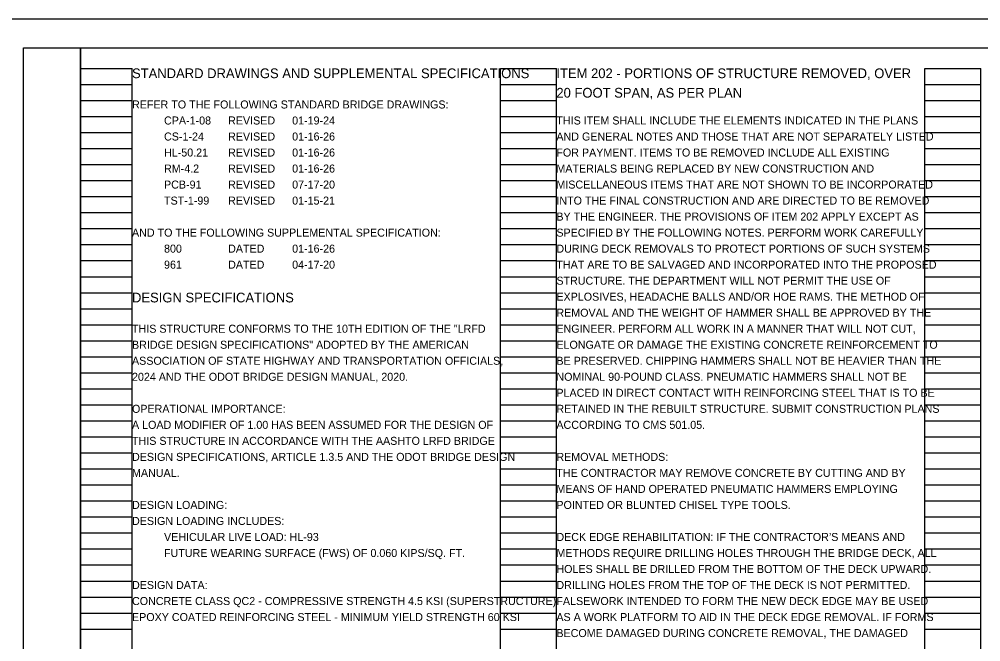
# Model space of a CAD drawing. Extents: x -16.5 to 61.9, y -20 to 22.7.
# Drawn here: x 0.43 to 17.24, y 11.12 to 22 of the extents above; entities that cross this region are included whole.
import ezdxf

# ---------------------------------------------------------------- set-up
doc = ezdxf.new("R2010")
doc.units = 0
for name, color, linetype in [('SH_Border', 7, 'Continuous'), ('SH_Cut_Line', 7, 'Continuous'), ('SH_Data', 7, 'Continuous'), ('SH_Text', 7, 'Continuous')]:
    doc.layers.add(name, color=color, linetype=linetype)

msp = doc.modelspace()

# ---------------------------------------------------------------- linework, layer by layer
at = {"layer": 'SH_Border'}
for points in [[(0.5, 21.5), (1.5, 21.5), (1.5, 0.5), (0.5, 0.5)], [(1.5, 21.5), (33.5, 21.5), (33.5, 0.5), (1.5, 0.5)]]:
    msp.add_lwpolyline(points, close=True, dxfattribs=at)
at = {"layer": 'SH_Cut_Line'}
msp.add_lwpolyline([(0, 0), (34, 0), (34, 22), (0, 22)], close=True, dxfattribs=at)
at = {"layer": 'SH_Data'}
for p, q in [((1.5, 0.98), (1.5, 21.14)), ((1.5, 21.14), (2.4, 21.14)), ((2.4, 0.98), (2.4, 21.14)), ((8.84, 0.98), (8.84, 21.14)), ((8.84, 21.14), (9.82, 21.14)), ((9.82, 0.98), (9.82, 21.14)), ((16.26, 0.98), (16.26, 21.14)), ((16.26, 21.14), (17.24, 21.14)), ((17.24, 0.98), (17.24, 21.14)), ((1.5, 20.86), (2.4, 20.86)), ((8.84, 20.86), (9.82, 20.86)), ((16.26, 20.86), (17.24, 20.86)), ((1.5, 20.58), (2.4, 20.58)), ((8.84, 20.58), (9.82, 20.58)), ((16.26, 20.58), (17.24, 20.58)), ((1.5, 20.3), (2.4, 20.3)), ((8.84, 20.3), (9.82, 20.3)), ((16.26, 20.3), (17.24, 20.3)), ((1.5, 20.02), (2.4, 20.02)), ((8.84, 20.02), (9.82, 20.02)), ((16.26, 20.02), (17.24, 20.02)), ((1.5, 19.74), (2.4, 19.74)), ((8.84, 19.74), (9.82, 19.74)), ((16.26, 19.74), (17.24, 19.74)), ((1.5, 19.46), (2.4, 19.46)), ((8.84, 19.46), (9.82, 19.46)), ((16.26, 19.46), (17.24, 19.46)), ((1.5, 19.18), (2.4, 19.18)), ((8.84, 19.18), (9.82, 19.18)), ((16.26, 19.18), (17.24, 19.18)), ((1.5, 18.9), (2.4, 18.9)), ((8.84, 18.9), (9.82, 18.9)), ((16.26, 18.9), (17.24, 18.9)), ((1.5, 18.62), (2.4, 18.62)), ((8.84, 18.62), (9.82, 18.62)), ((16.26, 18.62), (17.24, 18.62)), ((1.5, 18.34), (2.4, 18.34)), ((8.84, 18.34), (9.82, 18.34)), ((16.26, 18.34), (17.24, 18.34)), ((1.5, 18.06), (2.4, 18.06)), ((8.84, 18.06), (9.82, 18.06)), ((16.26, 18.06), (17.24, 18.06)), ((1.5, 17.78), (2.4, 17.78)), ((8.84, 17.78), (9.82, 17.78)), ((16.26, 17.78), (17.24, 17.78)), ((1.5, 17.5), (2.4, 17.5)), ((8.84, 17.5), (9.82, 17.5)), ((16.26, 17.5), (17.24, 17.5)), ((1.5, 17.22), (2.4, 17.22)), ((8.84, 17.22), (9.82, 17.22)), ((16.26, 17.22), (17.24, 17.22)), ((1.5, 16.94), (2.4, 16.94)), ((8.84, 16.94), (9.82, 16.94)), ((16.26, 16.94), (17.24, 16.94)), ((1.5, 16.66), (2.4, 16.66)), ((8.84, 16.66), (9.82, 16.66)), ((16.26, 16.66), (17.24, 16.66)), ((1.5, 16.38), (2.4, 16.38)), ((8.84, 16.38), (9.82, 16.38)), ((16.26, 16.38), (17.24, 16.38)), ((1.5, 16.1), (2.4, 16.1)), ((8.84, 16.1), (9.82, 16.1)), ((16.26, 16.1), (17.24, 16.1)), ((1.5, 15.82), (2.4, 15.82)), ((8.84, 15.82), (9.82, 15.82)), ((16.26, 15.82), (17.24, 15.82)), ((1.5, 15.54), (2.4, 15.54)), ((8.84, 15.54), (9.82, 15.54)), ((16.26, 15.54), (17.24, 15.54)), ((1.5, 15.26), (2.4, 15.26)), ((8.84, 15.26), (9.82, 15.26)), ((16.26, 15.26), (17.24, 15.26)), ((1.5, 14.98), (2.4, 14.98)), ((8.84, 14.98), (9.82, 14.98)), ((16.26, 14.98), (17.24, 14.98)), ((1.5, 14.7), (2.4, 14.7)), ((8.84, 14.7), (9.82, 14.7)), ((16.26, 14.7), (17.24, 14.7)), ((1.5, 14.42), (2.4, 14.42)), ((8.84, 14.42), (9.82, 14.42)), ((16.26, 14.42), (17.24, 14.42)), ((1.5, 14.14), (2.4, 14.14)), ((8.84, 14.14), (9.82, 14.14)), ((16.26, 14.14), (17.24, 14.14)), ((1.5, 13.86), (2.4, 13.86)), ((8.84, 13.86), (9.82, 13.86)), ((16.26, 13.86), (17.24, 13.86)), ((1.5, 13.58), (2.4, 13.58)), ((8.84, 13.58), (9.82, 13.58)), ((16.26, 13.58), (17.24, 13.58)), ((1.5, 13.3), (2.4, 13.3)), ((8.84, 13.3), (9.82, 13.3)), ((16.26, 13.3), (17.24, 13.3)), ((1.5, 13.02), (2.4, 13.02)), ((8.84, 13.02), (9.82, 13.02)), ((16.26, 13.02), (17.24, 13.02)), ((1.5, 12.74), (2.4, 12.74)), ((8.84, 12.74), (9.82, 12.74)), ((16.26, 12.74), (17.24, 12.74)), ((1.5, 12.46), (2.4, 12.46)), ((8.84, 12.46), (9.82, 12.46)), ((16.26, 12.46), (17.24, 12.46)), ((1.5, 12.18), (2.4, 12.18)), ((8.84, 12.18), (9.82, 12.18)), ((16.26, 12.18), (17.24, 12.18)), ((1.5, 11.9), (2.4, 11.9)), ((8.84, 11.9), (9.82, 11.9)), ((16.26, 11.9), (17.24, 11.9)), ((1.5, 11.62), (2.4, 11.62)), ((8.84, 11.62), (9.82, 11.62)), ((16.26, 11.62), (17.24, 11.62)), ((1.5, 11.34), (2.4, 11.34)), ((8.84, 11.34), (9.82, 11.34)), ((16.26, 11.34), (17.24, 11.34))]:
    msp.add_line(p, q, dxfattribs=at)

# ---------------------------------------------------------------- texts
at = {"layer": 'SH_Text'}
for s, height, p in [('STANDARD DRAWINGS AND SUPPLEMENTAL SPECIFICATIONS', 0.17, (2.4, 20.97)), ('ITEM 202 - PORTIONS OF STRUCTURE REMOVED, OVER ', 0.17, (9.82, 20.97)), ('20 FOOT SPAN, AS PER PLAN', 0.17, (9.82, 20.63)), ('REFER TO THE FOLLOWING STANDARD BRIDGE DRAWINGS:', 0.14, (2.4, 20.44)), ('CPA-1-08', 0.14, (2.96, 20.16)), ('REVISED', 0.14, (4.08, 20.16)), ('01-19-24', 0.14, (5.2, 20.16)), ('THIS ITEM SHALL INCLUDE THE ELEMENTS INDICATED IN THE PLANS ', 0.14, (9.82, 20.16)), ('CS-1-24', 0.14, (2.96, 19.88)), ('REVISED', 0.14, (4.08, 19.88)), ('01-16-26', 0.14, (5.2, 19.88)), ('AND GENERAL NOTES AND THOSE THAT ARE NOT SEPARATELY LISTED ', 0.14, (9.82, 19.88)), ('HL-50.21', 0.14, (2.96, 19.6)), ('REVISED', 0.14, (4.08, 19.6)), ('01-16-26', 0.14, (5.2, 19.6)), ('FOR PAYMENT. ITEMS TO BE REMOVED INCLUDE ALL EXISTING ', 0.14, (9.82, 19.6)), ('RM-4.2', 0.14, (2.96, 19.32)), ('REVISED', 0.14, (4.08, 19.32)), ('01-16-26', 0.14, (5.2, 19.32)), ('MATERIALS BEING REPLACED BY NEW CONSTRUCTION AND ', 0.14, (9.82, 19.32)), ('PCB-91', 0.14, (2.96, 19.04)), ('REVISED', 0.14, (4.08, 19.04)), ('07-17-20', 0.14, (5.2, 19.04)), ('MISCELLANEOUS ITEMS THAT ARE NOT SHOWN TO BE INCORPORATED ', 0.14, (9.82, 19.04)), ('TST-1-99', 0.14, (2.96, 18.76)), ('REVISED', 0.14, (4.08, 18.76)), ('01-15-21', 0.14, (5.2, 18.76)), ('INTO THE FINAL CONSTRUCTION AND ARE DIRECTED TO BE REMOVED ', 0.14, (9.82, 18.76)), ('BY THE ENGINEER. THE PROVISIONS OF ITEM 202 APPLY EXCEPT AS ', 0.14, (9.82, 18.48)), ('AND TO THE FOLLOWING SUPPLEMENTAL SPECIFICATION:', 0.14, (2.4, 18.2)), ('SPECIFIED BY THE FOLLOWING NOTES. PERFORM WORK CAREFULLY ', 0.14, (9.82, 18.2)), ('800', 0.14, (2.96, 17.92)), ('DATED', 0.14, (4.08, 17.92)), ('01-16-26', 0.14, (5.2, 17.92)), ('DURING DECK REMOVALS TO PROTECT PORTIONS OF SUCH SYSTEMS ', 0.14, (9.82, 17.92)), ('961', 0.14, (2.96, 17.64)), ('DATED', 0.14, (4.08, 17.64)), ('04-17-20', 0.14, (5.2, 17.64)), ('THAT ARE TO BE SALVAGED AND INCORPORATED INTO THE PROPOSED ', 0.14, (9.82, 17.64)), ('STRUCTURE. THE DEPARTMENT WILL NOT PERMIT THE USE OF ', 0.14, (9.82, 17.36)), ('DESIGN SPECIFICATIONS', 0.17, (2.4, 17.05)), ('EXPLOSIVES, HEADACHE BALLS AND/OR HOE RAMS. THE METHOD OF ', 0.14, (9.82, 17.08)), ('REMOVAL AND THE WEIGHT OF HAMMER SHALL BE APPROVED BY THE ', 0.14, (9.82, 16.8)), ('THIS STRUCTURE CONFORMS TO THE 10TH EDITION OF THE "LRFD ', 0.14, (2.4, 16.52)), ('ENGINEER. PERFORM ALL WORK IN A MANNER THAT WILL NOT CUT, ', 0.14, (9.82, 16.52)), ('BRIDGE DESIGN SPECIFICATIONS" ADOPTED BY THE AMERICAN ', 0.14, (2.4, 16.24)), ('ELONGATE OR DAMAGE THE EXISTING CONCRETE REINFORCEMENT TO ', 0.14, (9.82, 16.24)), ('ASSOCIATION OF STATE HIGHWAY AND TRANSPORTATION OFFICIALS,  ', 0.14, (2.4, 15.96)), ('BE PRESERVED. CHIPPING HAMMERS SHALL NOT BE HEAVIER THAN THE ', 0.14, (9.82, 15.96)), ('2024 AND THE ODOT BRIDGE DESIGN MANUAL, 2020.', 0.14, (2.4, 15.68)), ('NOMINAL 90-POUND CLASS. PNEUMATIC HAMMERS SHALL NOT BE ', 0.14, (9.82, 15.68)), ('PLACED IN DIRECT CONTACT WITH REINFORCING STEEL THAT IS TO BE ', 0.14, (9.82, 15.4)), ('OPERATIONAL IMPORTANCE:', 0.14, (2.4, 15.12)), ('RETAINED IN THE REBUILT STRUCTURE. SUBMIT CONSTRUCTION PLANS ', 0.14, (9.82, 15.12)), ('A LOAD MODIFIER OF 1.00 HAS BEEN ASSUMED FOR THE DESIGN OF ', 0.14, (2.4, 14.84)), ('ACCORDING TO CMS 501.05. ', 0.14, (9.82, 14.84)), ('THIS STRUCTURE IN ACCORDANCE WITH THE AASHTO LRFD BRIDGE ', 0.14, (2.4, 14.56)), ('DESIGN SPECIFICATIONS, ARTICLE 1.3.5 AND THE ODOT BRIDGE DESIGN ', 0.14, (2.4, 14.28)), ('REMOVAL METHODS:', 0.14, (9.82, 14.28)), ('MANUAL. ', 0.14, (2.4, 14)), ('THE CONTRACTOR MAY REMOVE CONCRETE BY CUTTING AND BY ', 0.14, (9.82, 14)), ('MEANS OF HAND OPERATED PNEUMATIC HAMMERS EMPLOYING ', 0.14, (9.82, 13.72)), ('DESIGN LOADING:', 0.14, (2.4, 13.44)), ('POINTED OR BLUNTED CHISEL TYPE TOOLS.', 0.14, (9.82, 13.44)), ('DESIGN LOADING INCLUDES:', 0.14, (2.4, 13.16)), ('VEHICULAR LIVE LOAD: HL-93', 0.14, (2.96, 12.88)), ('DECK EDGE REHABILITATION: IF THE CONTRACTOR’S MEANS AND ', 0.14, (9.82, 12.88)), ('FUTURE WEARING SURFACE (FWS) OF 0.060 KIPS/SQ. FT.', 0.14, (2.96, 12.6)), ('METHODS REQUIRE DRILLING HOLES THROUGH THE BRIDGE DECK, ALL ', 0.14, (9.82, 12.6)), ('HOLES SHALL BE DRILLED FROM THE BOTTOM OF THE DECK UPWARD. ', 0.14, (9.82, 12.32)), ('DESIGN DATA:', 0.14, (2.4, 12.04)), ('DRILLING HOLES FROM THE TOP OF THE DECK IS NOT PERMITTED. ', 0.14, (9.82, 12.04)), ('CONCRETE CLASS QC2 - COMPRESSIVE STRENGTH 4.5 KSI (SUPERSTRUCTURE)', 0.14, (2.4, 11.76)), ('FALSEWORK INTENDED TO FORM THE NEW DECK EDGE MAY BE USED ', 0.14, (9.82, 11.76)), ('EPOXY COATED REINFORCING STEEL - MINIMUM YIELD STRENGTH 60 KSI', 0.14, (2.4, 11.48)), ('AS A WORK PLATFORM TO AID IN THE DECK EDGE REMOVAL. IF FORMS ', 0.14, (9.82, 11.48)), ('BECOME DAMAGED DURING CONCRETE REMOVAL, THE DAMAGED ', 0.14, (9.82, 11.2))]:
    msp.add_text(s, height=height, dxfattribs=at).set_placement(p)

doc.saveas('drawing.dxf')
